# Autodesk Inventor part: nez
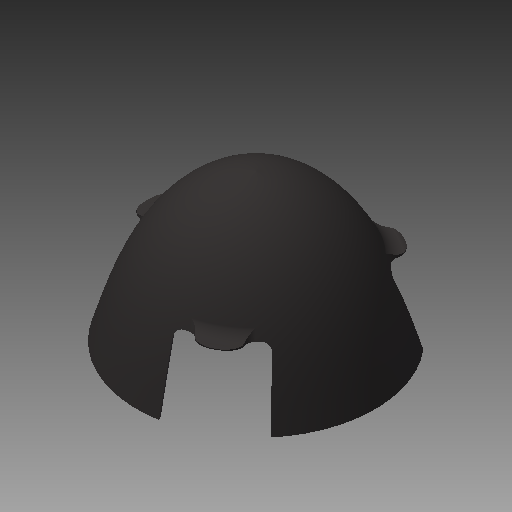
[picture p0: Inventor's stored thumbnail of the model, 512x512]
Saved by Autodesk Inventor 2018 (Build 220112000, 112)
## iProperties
Created: 2014-09
Part Number: nez
Material: Générique
Document SubType Name: Modeling
Designer: papa
Density: 1 g/cm^3
Appearance: Par défaut
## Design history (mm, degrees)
node "nez1"
node "nez"
node "Base1"
